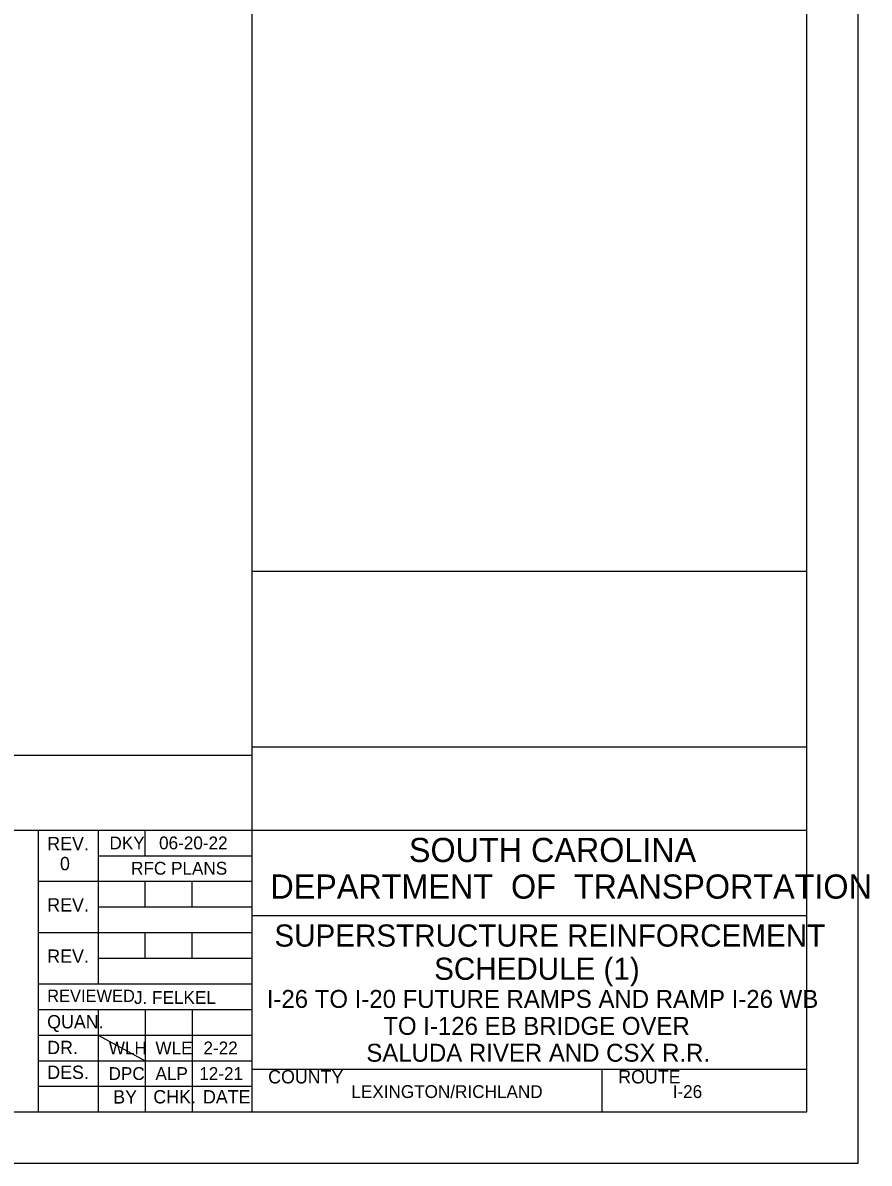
# Model space of a CAD drawing. Extents: x -133.1 to -97, y -1.7 to 20.6.
# Drawn here: x -105.3 to -97.03, y -1.69 to 9.43 of the extents above; entities that cross this region are included whole.
import ezdxf

# ---------------------------------------------------------------- set-up
doc = ezdxf.new("R2010")
doc.units = 0
for name, color, linetype in [('BR_AUTO DIMENSION', 7, 'Continuous'), ('BR_BORDER LINES', 7, 'Continuous'), ('BR_TEXT', 7, 'Continuous'), ('Level 31', 7, 'Continuous')]:
    doc.layers.add(name, color=color, linetype=linetype)

msp = doc.modelspace()

# ---------------------------------------------------------------- linework, layer by layer
at = {"layer": 'BR_AUTO DIMENSION'}
msp.add_lwpolyline([(-112.369, 2.291), (-103.058, 2.291), (-103.058, 19.042), (-112.369, 19.042)], close=True, dxfattribs=at)
at = {"layer": 'BR_BORDER LINES'}
for p, q in [((-97.642, -1.191), (-97.642, 19.809)), ((-103.058, -1.191), (-103.058, 4.086)), ((-103.058, 4.086), (-97.642, 4.086)), ((-103.058, 2.371), (-97.642, 2.371)), ((-110.507, 1.559), (-105.142, 1.559)), ((-105.142, -1.191), (-105.142, 1.559)), ((-105.142, 1.559), (-97.642, 1.559)), ((-104.559, 1.559), (-104.559, 0.059)), ((-104.1, 1.309), (-104.1, 1.559)), ((-104.559, 1.309), (-103.058, 1.309)), ((-105.142, 1.059), (-103.058, 1.059)), ((-104.1, 0.809), (-104.1, 1.059)), ((-103.642, 0.809), (-103.642, 1.059)), ((-104.559, 0.809), (-103.058, 0.809)), ((-103.058, 0.726), (-103.058, 0.726)), ((-103.058, 0.726), (-97.641, 0.726)), ((-105.142, 0.559), (-103.058, 0.559)), ((-104.1, 0.309), (-104.1, 0.559)), ((-103.642, 0.309), (-103.642, 0.559)), ((-104.559, 0.309), (-103.058, 0.309)), ((-105.142, 0.059), (-103.058, 0.059)), ((-105.142, -0.191), (-103.058, -0.191)), ((-104.559, -0.191), (-104.559, -1.191)), ((-104.1, -0.191), (-104.1, -1.191)), ((-103.642, -0.191), (-103.642, -1.191)), ((-105.142, -0.441), (-103.058, -0.441)), ((-105.142, -0.691), (-103.058, -0.691)), ((-103.058, -0.774), (-97.642, -0.774)), ((-102.961, -0.774), (-97.642, -0.774)), ((-99.642, -1.191), (-99.642, -0.774)), ((-105.142, -0.941), (-103.058, -0.941)), ((-131.308, -1.191), (-97.642, -1.191))]:
    msp.add_line(p, q, dxfattribs=at)
at = {"layer": 'Level 31'}
for p, q in [((-100.35, 0.285), (-100.35, 0.285)), ((-104.559, -0.441), (-104.1, -0.691))]:
    msp.add_line(p, q, dxfattribs=at)
msp.add_lwpolyline([(-133.141, -1.691), (-97.141, -1.691), (-97.141, 20.309), (-133.141, 20.309)], close=True, dxfattribs=at)

# ---------------------------------------------------------------- texts
at = {"layer": 'BR_TEXT'}
for s, height, p in [('REV.', 0.13, (-105.057, 1.362)), ('DKY', 0.125, (-104.45, 1.371)), ('06-20-22', 0.125, (-103.966, 1.371)), ('SOUTH CAROLINA', 0.23587, (-101.527, 1.247)), ('0', 0.13, (-104.933, 1.167)), ('RFC PLANS', 0.125, (-104.239, 1.124)), ('DEPARTMENT  OF  TRANSPORTATION', 0.23587, (-102.879, 0.89)), ('REV.', 0.13, (-105.057, 0.764)), ('SUPERSTRUCTURE REINFORCEMENT', 0.216, (-102.84, 0.422)), ('REV.', 0.13, (-105.057, 0.264)), ('SCHEDULE (1)', 0.216, (-101.281, 0.098)), ('REVIEWED', 0.12, (-105.058, -0.118)), ('I-26 TO I-20 FUTURE RAMPS AND RAMP I-26 WB', 0.175, (-102.915, -0.176)), ('J. FELKEL', 0.125, (-104.211, -0.137)), ('QUAN.', 0.13, (-105.058, -0.376)), ('TO I-126 EB BRIDGE OVER', 0.175, (-101.777, -0.439)), ('DR.', 0.13, (-105.058, -0.627)), ('WLH', 0.125, (-104.457, -0.629)), ('WLE', 0.125, (-104.001, -0.629)), ('2-22', 0.125, (-103.533, -0.629)), ('SALUDA RIVER AND CSX R.R.', 0.175, (-101.943, -0.701)), ('DES.', 0.13, (-105.057, -0.869)), ('DPC', 0.125, (-104.459, -0.879)), ('ALP', 0.125, (-104.001, -0.879)), ('12-21', 0.125, (-103.574, -0.879)), ('COUNTY', 0.13, (-102.901, -0.913)), ('ROUTE', 0.13, (-99.484, -0.913)), ('BY', 0.13, (-104.413, -1.109)), ('CHK.', 0.13, (-104.022, -1.108)), ('DATE', 0.13, (-103.537, -1.108)), ('LEXINGTON/RICHLAND', 0.12499, (-102.089, -1.055)), ('I-26', 0.125, (-98.953, -1.055))]:
    msp.add_text(s, height=height, dxfattribs=at).set_placement(p)

doc.saveas('drawing.dxf')
